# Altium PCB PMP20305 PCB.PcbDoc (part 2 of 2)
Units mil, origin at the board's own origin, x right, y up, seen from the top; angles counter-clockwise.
Board outline 4400 x 7000 mil, 4 copper layers (Top Layer, GND, Signal Layer 2, Bottom Layer), stack 61.2 mil thick; 121 components, 72 nets, 974 pads, 10 vias.
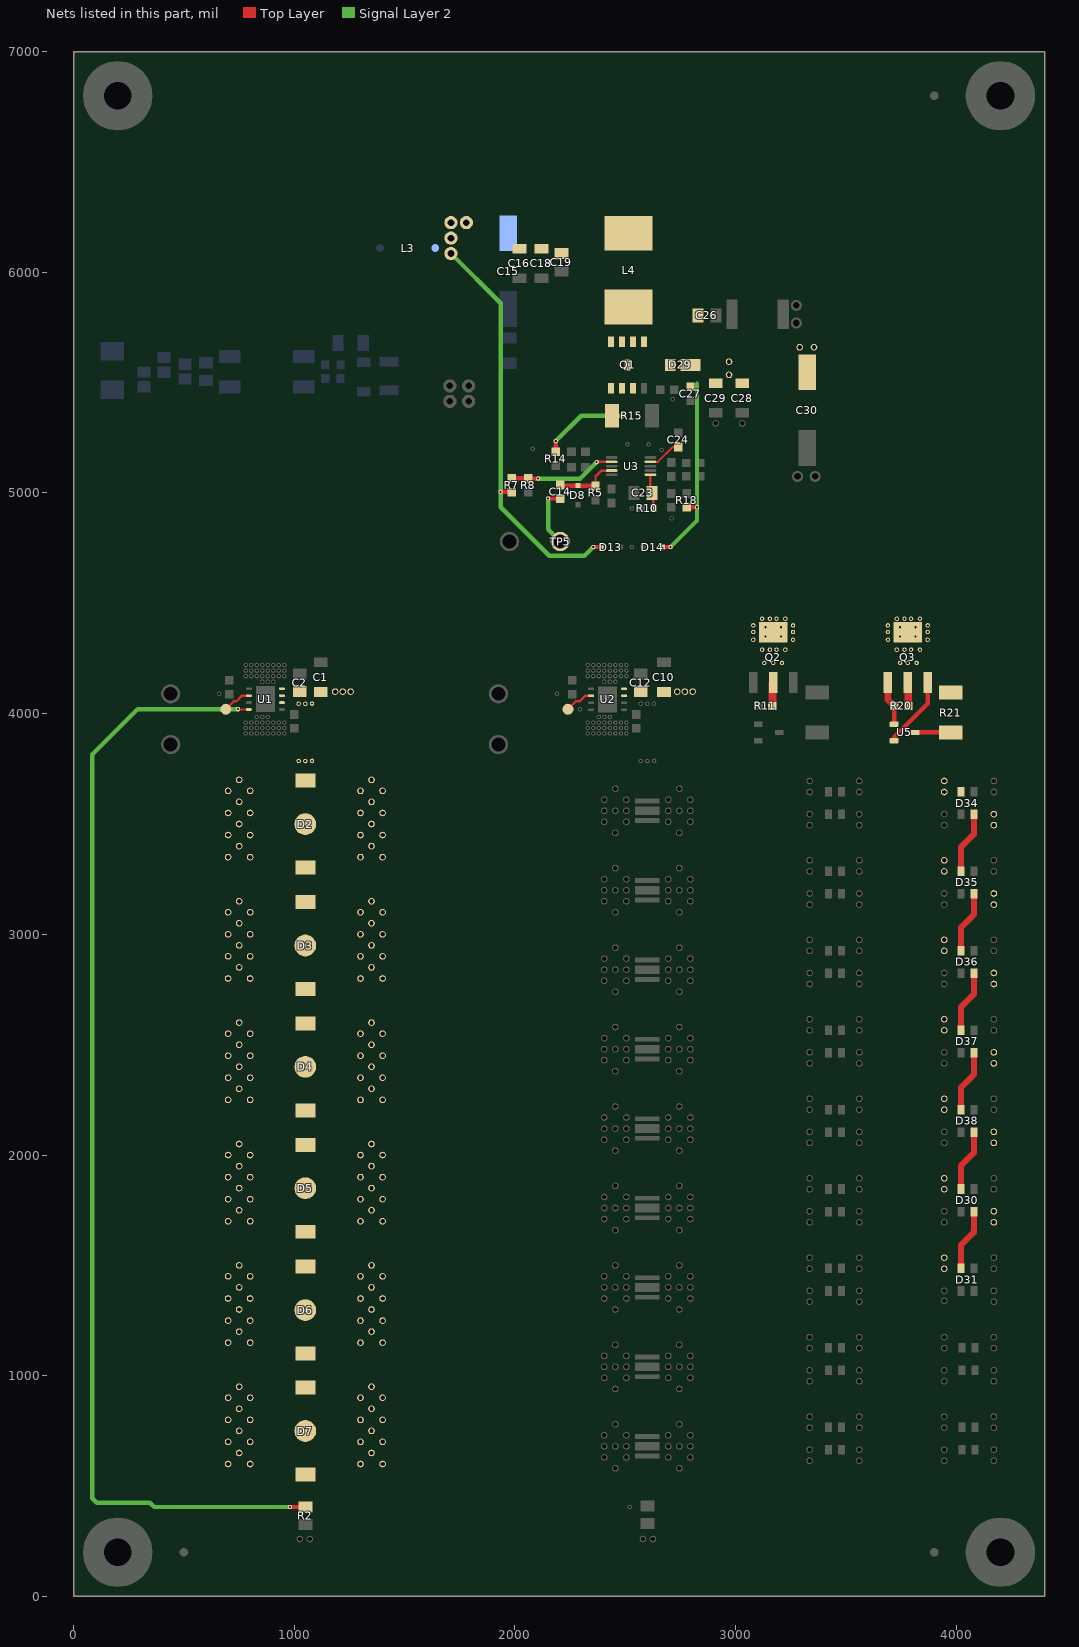
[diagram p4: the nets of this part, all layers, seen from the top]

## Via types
v1: diameter 20, hole 10, Top Layer to Bottom Layer, 10 vias

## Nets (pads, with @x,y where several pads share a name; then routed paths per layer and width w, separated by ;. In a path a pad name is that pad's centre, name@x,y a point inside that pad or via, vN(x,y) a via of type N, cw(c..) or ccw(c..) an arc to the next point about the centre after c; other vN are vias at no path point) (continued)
RED3_3: D30.2 D31.4 pad.124 pad.125 pad.128 pad.129 | length 282.1
  Top Layer w28: D31.4@4020.47,1486.18 4020.47,1590.47 4079.53,1649.53 D30.2@4079.53,1743.82
RED3_4: D30.4 D38.2 pad.132 pad.133 pad.136 pad.137 | length 282.1
  Top Layer w28: D30.4@4020.47,1846.18 4020.47,1950.47 4079.53,2009.53 D38.2@4079.53,2103.82
RED3_5: D37.2 D38.4 pad.140 pad.141 pad.144 pad.145 | length 282.1
  Top Layer w28: D38.4@4020.47,2206.18 4020.47,2305.47 4079.53,2364.53 D37.2@4079.53,2463.82
RED3_6: D36.2 D37.4 pad.148 pad.149 pad.152 pad.153 | length 282.1
  Top Layer w28: D37.4@4020.47,2566.18 4020.47,2670.47 4079.53,2729.53 D36.2@4079.53,2823.82
RED3_7: D35.2 D36.4 pad.158 pad.159 pad.162 pad.163 | length 282.1
  Top Layer w28: D36.4@4020.47,2926.18 4020.47,3030.47 4079.53,3089.53 D35.2@4079.53,3183.82
RED3_8: D34.2 D35.4 pad.166 pad.167 pad.170 pad.171 | length 282.1
  Top Layer w28: D35.4@4020.47,3286.18 4020.47,3394.54 4079.53,3453.59 D34.2@4079.53,3543.82
RED3_9: D34.4 pad.174 pad.175 R21.1 U5.3 | length 162.2
  Top Layer w20: U5.3@3812.24,3915 R21.1@3974.45,3915
RED3_BASE: Q3.1 R20.1 U5.1 | length 201
  Top Layer w10: Q3.1@3688.5,4139.88 Q3.1@3689.45,4140.83
  Top Layer w20: U5.1@3717.76,3952.4 R20.1@3717.76,4034.25
  Top Layer w30: Q3.1@3689.45,4140.83 3689.45,4064.06 R20.1@3718.5,4035
RED3_SNS: Q3.3 R21.2 U5.2 | length 326.5
  Top Layer w20: U5.2@3717.76,3877.6 3717.76,3892.76 3870.55,4045.55 Q3.3@3870.55,4140.83
RSNS: pad.6@2185,5235 pad.6@2490,5350 Q1.1 Q1.2 Q1.3 R14.2 R15.2 | length 404
  Top Layer w10: R14.2@2175.98,5182.78 R14.2@2177.98,5184.77
  Top Layer w20: R14.2@2185,5186.5 pad.6@2185,5235
  Signal Layer 2 w20: pad.6@2185,5235 2300,5350 pad.6@2490,5350
ST_RED: pad.0@2240,4020 U2.2 | length 130.4
  Top Layer w11: pad.0@2240,4020 2275.44,4055.44 2292.07,4055.44 2317.38,4080.75 U2.2@2345.2,4080.75
ST_YEL: pad.0@690,4020 U1.2 | length 129.7
  Top Layer w11: pad.0@690,4020 725.44,4055.44 737.07,4055.44 763.44,4081.81 U1.2@794.14,4081.81
SW: C26.2 D29.2 L4.2 Q1.5 Q1.6 Q1.7 Q1.8 Q1.9
SYNC: C14.2 D8.1 R5.2 U3.9 | length 284.5
  Top Layer w10: U3.9@2437.8,5100.69 U3.9@2438.7,5101.59
  Top Layer w11: R5.2@2365,5031.5 2365,5075 2391.59,5101.59 U3.9@2438.7,5101.59
  Top Layer w20: C14.2@2208.19,5033.31 D8.1@2285,5033.31 R5.2@2363.19,5033.31
SYNCIN: C14.1 pad.6@2150,4975 TP5.1 | length 271.3
  Top Layer w20: pad.6@2150,4975 C14.1@2203.5,4975
  Signal Layer 2 w20: pad.6@2150,4975 2150,4835 TP5.1@2205,4780
UVLO: pad.6@2105,5065 pad.6@2370,5140 R7.1 R8.2 U3.7 | length 482.3
  Top Layer w11: pad.6@2370.96,5140.96 U3.7@2438.7,5140.96
  Top Layer w20: R7.1@1985,5066.5 R8.2@2060,5066.5 ; R8.2@2061.5,5065 pad.6@2105,5065
  Signal Layer 2 w20: pad.6@2105,5065 2295,5065 pad.6@2370,5140
V_BOOST: C1.1 C2.1 C10.1 C12.1 C27.1 C28.1 C29.1 C30.1 D14.2 D29.1 pad.6@2705,4755 pad.6@2825,4935 pad.180 pad.181 pad.182 pad.183 pad.188 pad.189 pad.190 pad.191 pad.192 pad.193 pad.194 pad.195 pad.214 pad.215 pad.216 pad.217 pad.218 pad.219 pad.224 pad.225 Q2.2 Q2.4 Q3.2 Q3.4 R11.2 R18.2 R20.2 U1.7 U1.8 U2.7 U2.8 | length 1079.9
  Top Layer w20: D14.2@2668.31,4755 pad.6@2705,4755 ; R18.2@2778.19,4935 pad.6@2825,4935
  Top Layer w35: R11.2@3166.5,4035 Q2.2@3166.5,4137.32 ; R20.2@3781.5,4035 Q3.2@3781.5,4139.33
  Signal Layer 2 w20: pad.6@2705,4755 2825,4875 pad.6@2825,4935 2825,5495
VCC: C24.2 U3.4 | length 155.4
  Top Layer w10: U3.4@2614.8,5141.87 U3.4@2613.9,5140.96 2647.38,5140.96 2714.92,5208.5 C24.2@2740,5208.5
VIN: C15.1 C16.1 C18.1 C19.1 D13.2 L3.2 L4.1 pad.6@1935,5005 pad.6@2355,4755 pad.198@1710,6225 pad.199@1710,6085 pad.200@1780,6225 pad.201@1710,6155 R7.2 | length 1856.1
  Top Layer w20: pad.6@1935,5005 R7.2@1983.5,5005 ; pad.6@2355,4755 D13.2@2391.69,4755
  Signal Layer 2 w20: pad.199@1710,6085 1935,5860 pad.6@1935,5005 1935,4935 2155,4715 2315,4715 pad.6@2355,4755
VIN_IC: C23.1 R10.1 U3.1 | length 146.9
  Top Layer w11: U3.1@2613.9,5081.91 2613.9,5006.1 C23.1@2620,5000 ; R10.1@2627.56,4930 C23.1@2627.56,4992.44
YEL_1: D6.2 D7.1 pad.176@700,900 pad.176@750,950 pad.176@800,900 pad.176@1300,900 pad.176@1350,950 pad.176@1400,900 pad.177@700,800 pad.177@750,850 pad.177@800,800 pad.177@1300,800 pad.177@1350,850 pad.177@1400,800 pad.178@700,700 pad.178@750,750 pad.178@800,700 pad.178@1300,700 pad.178@1350,750 pad.178@1400,700 pad.179@700,600 pad.179@750,650 pad.179@800,600 pad.179@1300,600 pad.179@1350,650 pad.179@1400,600
YEL_2: D5.2 D6.1 pad.176@700,1450 pad.176@750,1500 pad.176@800,1450 pad.176@1300,1450 pad.176@1350,1500 pad.176@1400,1450 pad.177@700,1350 pad.177@750,1400 pad.177@800,1350 pad.177@1300,1350 pad.177@1350,1400 pad.177@1400,1350 pad.178@700,1250 pad.178@750,1300 pad.178@800,1250 pad.178@1300,1250 pad.178@1350,1300 pad.178@1400,1250 pad.179@700,1150 pad.179@750,1200 pad.179@800,1150 pad.179@1300,1150 pad.179@1350,1200 pad.179@1400,1150
YEL_3: D4.2 D5.1 pad.176@700,2000 pad.176@750,2050 pad.176@800,2000 pad.176@1300,2000 pad.176@1350,2050 pad.176@1400,2000 pad.177@700,1900 pad.177@750,1950 pad.177@800,1900 pad.177@1300,1900 pad.177@1350,1950 pad.177@1400,1900 pad.178@700,1800 pad.178@750,1850 pad.178@800,1800 pad.178@1300,1800 pad.178@1350,1850 pad.178@1400,1800 pad.179@700,1700 pad.179@750,1750 pad.179@800,1700 pad.179@1300,1700 pad.179@1350,1750 pad.179@1400,1700
YEL_4: D3.2 D4.1 pad.176@700,2550 pad.176@750,2600 pad.176@800,2550 pad.176@1300,2550 pad.176@1350,2600 pad.176@1400,2550 pad.177@700,2450 pad.177@750,2500 pad.177@800,2450 pad.177@1300,2450 pad.177@1350,2500 pad.177@1400,2450 pad.178@700,2350 pad.178@750,2400 pad.178@800,2350 pad.178@1300,2350 pad.178@1350,2400 pad.178@1400,2350 pad.179@700,2250 pad.179@750,2300 pad.179@800,2250 pad.179@1300,2250 pad.179@1350,2300 pad.179@1400,2250
YEL_5: D2.2 D3.1 pad.176@700,3100 pad.176@750,3150 pad.176@800,3100 pad.176@1300,3100 pad.176@1350,3150 pad.176@1400,3100 pad.177@700,3000 pad.177@750,3050 pad.177@800,3000 pad.177@1300,3000 pad.177@1350,3050 pad.177@1400,3000 pad.178@700,2900 pad.178@750,2950 pad.178@800,2900 pad.178@1300,2900 pad.178@1350,2950 pad.178@1400,2900 pad.179@700,2800 pad.179@750,2850 pad.179@800,2800 pad.179@1300,2800 pad.179@1350,2850 pad.179@1400,2800
YEL_6: D2.1 pad.1@1020,3785.49 pad.1@1020,4045 pad.1@1050,3785 pad.1@1050,4044.51 pad.1@1080.49,3785.98 pad.1@1080.49,4045.49 pad.176@700,3650 pad.176@750,3700 pad.176@800,3650 pad.176@1300,3650 pad.176@1350,3700 pad.176@1400,3650 pad.177@700,3550 pad.177@750,3600 pad.177@800,3550 pad.177@1300,3550 pad.177@1350,3600 pad.177@1400,3550 pad.178@700,3450 pad.178@750,3500 pad.178@800,3450 pad.178@1300,3450 pad.178@1350,3500 pad.178@1400,3450 pad.179@700,3350 pad.179@750,3400 pad.179@800,3350 pad.179@1300,3350 pad.179@1350,3400 pad.179@1400,3350 U1.6
YEL_SNS: D7.2 pad.1@745,4020.49 pad.1@980,405 R2.2 U1.4 | length 5143.5
  Top Layer w11: pad.1@746.67,4018.82 U1.4@794.14,4018.82
  Top Layer w20: pad.1@980,405 R2.2@1050,405
  Signal Layer 2 w20: pad.1@744.51,4020 290,4020 85,3815 85,445 105,425 345,425 365,405 pad.1@980,405
pads on no net: D20.1 D20.3 D21.1 D21.3 D22.1 D22.3 D23.1 D23.3 D24.1 D24.3 D25.1 D25.3 D26.1 D26.3 D27.1 D27.3 D28.1 D28.3 D30.1 D30.3 D31.1 D31.3 D32.1 D32.3 D33.1 D33.3 D34.1 D34.3 D35.1 D35.3 D36.1 D36.3 D37.1 D37.3 D38.1 D38.3 FID1.1 FID2.1 FID3.1 H1.1 H2.1 H3.1 H4.1 H5.0 H6.0 H7.0 H8.0 LBL1.0

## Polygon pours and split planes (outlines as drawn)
RED1_9 on Top Layer "TopLayer-RED1_9" (solid, remove dead copper, pour order 294): 2485,4045 2485,4060 2655,4060 2655,4035 2485,4035 2485,4045
YEL_6 on Top Layer "TopLayer-YEL_6" (solid, remove dead copper, pour order 136): 930,4050 930,4060 1015,4060 1095,4060 1095,4035 930,4035 930,4050
GND on Top Layer "Top Layer-GND" (solid, remove dead copper, pour order 296): 1650,7000 4400,7000 4400,4720 4400,0 0,0 0,5050 1650,5050 1650,5350
V_BOOST on Top Layer "Top Layer-Vboost" (solid, remove dead copper, pour order 106): 2750,5700 2750,5460 3400,5460 3400,4500 2990,4500 2990,3990 3400,3990 4400,3990 4400,5460 4400,5700
SW on Top Layer "Top Layer-SW" (solid, remove dead copper, pour order 105): 2395,5920 2730,5920 2730,5835 2855,5835 2855,5775 2730,5775 2730,5530 2395,5530
FB on Top Layer "Top Layer-FB" (solid, remove dead copper, pour order 102): 2800,5095 2800,4976.28 2689.28,4976.28 2689.28,5084.63 2689.28,5090 2689.28,5095
VIN on Top Layer "Top Layer-VIN" (solid, remove dead copper, pour order 101): 1652.5,6255 2627.5,6255 2627.5,6050 2017.5,6050 1652.5,6050
RSNS on Top Layer "Bottom Layer-Rsns" (solid, remove dead copper, pour order 104): 2390,5500 2390,5295 2550,5295 2550,5500
HS on Top Layer "Top Layer-HS" (solid, remove dead copper, pour order 131): 3100,3750 3100,500 2100,500 2100,3750
YEL_6 on Top Layer "Top Layer-YEL_6" (solid, remove dead copper, pour order 125): 150,3775 1950,3775 1950,3235 150,3235
YEL_5 on Top Layer "Top Layer-YEL_5" (solid, remove dead copper, pour order 126): 150,3215 150,2685 1950,2685 1950,3215
YEL_4 on Top Layer "Top Layer-YEL_4" (solid, remove dead copper, pour order 127): 150,2650 150,2665 1950,2665 1950,2650 1950,2135 150,2135
YEL_3 on Top Layer "Top Layer-YEL_3" (solid, remove dead copper, pour order 128): 150,2115 1950,2115 1950,1585 150,1585
YEL_2 on Top Layer "Top Layer-YEL_2" (solid, remove dead copper, pour order 129): 150,1565 150,1035 1950,1035 1950,1565
YEL_1 on Top Layer "Top Layer-YEL_1" (solid, remove dead copper, pour order 130): 150,1015 1950,1015 1950,475 150,475
V_BOOST on Top Layer "TopLayer-V_BOOST_YEL" (solid, remove dead copper, pour order 132): 930,4115 930,4125 1275,4125 1275,4105 1275,4075 970,4075 930,4075
V_BOOST on Top Layer "TopLayer-V_BOOST_RED1" (solid, remove dead copper, pour order 134): 2485,4125 2830,4125 2830,4075 2485,4075
GND on Bottom Layer "BottomLayer-GND" (solid, remove dead copper, pour order 324): 0,5050 1650,5050 1650,5225.25 1650,5377.5 1272.5,5377.5 1000,5377.5 1000,5505 1125,5505 1125,5535 1215.65,5535 1270.65,5480 1460,5480 1650,5480 1650,5615 1650,7000 4400,7000 4400,0 0,0
BEAD_OUT on Bottom Layer "BottomLayer-BEAD_OUT" (solid, remove dead copper, pour order 320): 1475,5570 1285,5570 1285,5715 1370,5715 1370,6260 1475,6260 1475,5865
CM_OUT on Bottom Layer "BottomLayer-CM_OUT" (solid, remove dead copper, pour order 318): 1230,5565 1120,5565 1120,5590 995,5590 995,5650 1170,5650 1170,5715 1230,5715 1230,5565
GNDIN on Bottom Layer "BottomLayer-GNDin" (solid, remove dead copper, pour order 316): 755,5495 755,5510 635,5510 635,5535 535,5535 535,5540 475,5540 475,5505 240,5505 85,5505 85,5150 400,5150 400,5240 400,5450 695,5450 755,5450
CM_IN on Bottom Layer "BottomLayer-CM_IN" (solid, remove dead copper, pour order 314): 755,5590 635,5590 635,5565 535,5565 535,5560 475,5560 475,5590 380,5590 380,5600 370,5600 85,5600 85,6000 400,6000 400,5650 755,5650 755,5590
VIN on Bottom Layer "BottomLayer-VIN" (solid, remove dead copper, pour order 322): 1655,5960 1555.42,5960 1555.42,5984.48 1555.42,6260 2015.42,6260 2015.42,5984.48 2015.42,5960
RED1_9 on Signal Layer 2 "SignalLayer2-RED1_9" (solid, remove dead copper, pour order 308): 2545,4060 2655,4060 2655,3890 2655,3625 2655,3585 2545,3585 2545,3605 2545,3725 2545,4000
YEL_6 on Signal Layer 2 "SignalLayer2-YEL_6" (solid, remove dead copper, pour order 306): 1005,4060 1095,4060 1095,3805 1095,3765 1005,3765 1005,3995
GND on Signal Layer 2 "SignalLayer2-GND" (solid, remove dead copper, pour order 312): 1650,5050 1650,5350 1650,7000 4400,7000 4400,0 0,0 0,5050
V_BOOST on Signal Layer 2 "SignalLayer2-V_BOOST" (solid, remove dead copper, pour order 304): 2750,5460 2750,5540 2750,5700 4400,5700 4400,5645 4400,3990 3680,3990 2990,3990 2990,4235 2825,4235 2825,4075 2715,4075 2715,4380 1275,4380 1275,4075 1165,4075 1165,4500 2990,4500 3400,4500 3400,5460 3385,5460
GND on GND "SignalLayer1-GND" (solid, remove dead copper, pour order 300): 0,5050 1650,5050 1650,7000 4400,7000 4400,0 0,0

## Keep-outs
Keep-Out Layer:
  the board outline again, w10
  text ".Layer_Name" at 577,-858.49 h60

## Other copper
Top Layer:
  rectangle net RED2_9: 3315,3680 3435,3945
  rectangle net RED2_SNS: 3240,4060 3425,4190
  rectangle net RED3_9: 3920,3680 4035,3945
  rectangle net RED3_SNS: 3850,4065 4030,4190
  rectangle net RED1_9: 2545,3595 2655,3800
  rectangle net YEL_6: 1005,3665 1095,3800
  rectangle net RED2_1: 3465,920 3725,1045
  rectangle net RED2_2: 3465,1280 3725,1405
  rectangle net RED2_3: 3465,1640 3725,1765
  rectangle net RED2_4: 3465,2000 3725,2125
  rectangle net RED2_5: 3465,2360 3725,2485
  rectangle net RED2_6: 3465,2720 3725,2845
  rectangle net RED2_7: 3465,3080 3725,3205
  rectangle net RED2_8: 3465,3440 3725,3565
  rectangle net RED3_8: 4065,3440 4325,3565
  rectangle net RED3_7: 4065,3080 4325,3205
  rectangle net RED3_6: 4065,2720 4325,2845
  rectangle net RED3_5: 4065,2360 4325,2485
  rectangle net RED3_4: 4065,2000 4325,2125
  rectangle net RED3_3: 4065,1640 4325,1765
  rectangle net RED3_2: 4065,1280 4325,1405
  rectangle net RED3_1: 4070,920 4325,1045
  rectangle net RED3_1: 3775,745 4040,870
  rectangle net RED3_2: 3775,1105 4040,1230
  rectangle net RED3_3: 3775,1465 4035,1590
  rectangle net RED3_4: 3775,1825 4035,1950
  rectangle net RED3_5: 3775,2185 4035,2310
  rectangle net RED3_6: 3775,2545 4035,2670
  rectangle net RED3_7: 3775,2905 4035,3030
  rectangle net RED3_8: 3775,3265 4035,3390
  rectangle net RED3_9: 3775,3625 4035,3750
  rectangle net RED2_9: 3175,3625 3435,3750
  rectangle net RED2_8: 3175,3265 3435,3390
  rectangle net RED2_7: 3175,2905 3435,3030
  rectangle net RED2_6: 3175,2545 3435,2670
  rectangle net RED2_5: 3175,2185 3435,2310
  rectangle net RED2_4: 3175,1825 3435,1950
  rectangle net RED2_3: 3175,1465 3435,1590
  rectangle net RED2_2: 3175,1105 3435,1230
  rectangle net RED2_1: 3175,745 3435,870
  rectangle: 3775,3440 4035,3565
  rectangle: 3775,3080 4035,3205
  rectangle: 3775,2720 4035,2845
  rectangle: 3775,2360 4035,2485
  rectangle: 3775,2000 4035,2125
  rectangle: 3775,1640 4035,1765
  rectangle: 3775,1280 4035,1405
  rectangle: 3775,920 4040,1045
  rectangle: 3775,560 4040,685
  rectangle: 3175,560 3435,685
  rectangle: 3175,920 3435,1045
  rectangle: 3175,1280 3435,1405
  rectangle: 3175,1640 3435,1765
  rectangle: 3175,2000 3435,2125
  rectangle: 3175,2360 3435,2485
  rectangle: 3175,2720 3435,2845
  rectangle: 3175,3080 3435,3205
  rectangle: 3175,3440 3435,3565
  rectangle: 4065,3625 4325,3750
  rectangle: 4065,3265 4325,3390
  rectangle: 4065,2905 4325,3030
  rectangle: 4065,2545 4325,2670
  rectangle: 4065,2185 4325,2310
  rectangle: 4065,1825 4325,1950
  rectangle: 4065,1465 4325,1590
  rectangle: 4070,1105 4325,1230
  rectangle: 4070,745 4325,870
  rectangle: 3465,3625 3725,3750
  rectangle: 3465,3265 3725,3390
  rectangle: 3465,2905 3725,3030
  rectangle: 3465,2545 3725,2670
  rectangle: 3465,2185 3725,2310
  rectangle: 3465,1825 3725,1950
  rectangle: 3465,1465 3725,1590
  rectangle: 3465,1105 3725,1230
  rectangle: 3465,745 3725,870
  rectangle net YEL_SNS: 1005,380 1095,580
  rectangle net RED1_SNS: 2545,385 2655,645
  rectangle net YEL_1: 1005,915 1095,1130
  rectangle net YEL_2: 1005,1465 1095,1680
  rectangle net YEL_3: 1005,2015 1095,2230
  rectangle net YEL_4: 1005,2565 1095,2780
  rectangle net YEL_5: 1005,3115 1095,3330
  rectangle net RED1_1: 2545,715 2655,1005
  rectangle net RED1_2: 2545,1075 2655,1365
  rectangle net RED1_3: 2545,1435 2655,1725
  rectangle net RED1_4: 2545,1795 2655,2085
  rectangle net RED1_5: 2545,2155 2655,2445
  rectangle net RED1_6: 2545,2515 2655,2805
  rectangle net RED1_7: 2545,2875 2655,3165
  rectangle net RED1_8: 2545,3235 2655,3525
  text ".Layer_Name" at 577,-858.49 h60
GND:
  rectangle net RED3_8: 4065,3440 4325,3565
  rectangle net RED3_7: 4065,3080 4325,3205
  rectangle net RED3_6: 4065,2720 4325,2845
  rectangle net RED3_5: 4065,2360 4325,2485
  rectangle net RED3_4: 4065,2000 4325,2125
  rectangle net RED3_3: 4065,1640 4325,1765
  rectangle net RED3_2: 4065,1280 4325,1405
  rectangle net RED2_2: 3465,1280 3725,1405
  rectangle net RED2_3: 3465,1640 3725,1765
  rectangle net RED2_4: 3465,2000 3725,2125
  rectangle net RED2_5: 3465,2360 3725,2485
  rectangle net RED2_6: 3465,2720 3725,2845
  rectangle net RED2_7: 3465,3080 3725,3205
  rectangle net RED2_8: 3465,3440 3725,3565
  rectangle: 3775,560 4040,685
  rectangle net RED3_1: 3775,745 4040,870
  rectangle: 4070,745 4325,870
  rectangle net RED3_1: 4070,920 4325,1045
  rectangle: 3775,920 4040,1045
  rectangle net RED3_2: 3775,1105 4040,1230
  rectangle: 4070,1105 4325,1230
  rectangle: 3775,1280 4035,1405
  rectangle net RED3_3: 3775,1465 4035,1590
  rectangle: 4065,1465 4325,1590
  rectangle: 3775,1640 4035,1765
  rectangle net RED3_4: 3775,1825 4035,1950
  rectangle: 4065,1825 4325,1950
  rectangle: 3775,2000 4035,2125
  rectangle net RED3_5: 3775,2185 4035,2310
  rectangle: 4065,2185 4325,2310
  rectangle: 3775,2360 4035,2485
  rectangle net RED3_6: 3775,2545 4035,2670
  rectangle: 4065,2545 4325,2670
  rectangle: 3775,2720 4035,2845
  rectangle: 4065,2905 4325,3030
  rectangle net RED3_7: 3775,2905 4035,3030
  rectangle: 3775,3080 4035,3205
  rectangle: 4065,3265 4325,3390
  rectangle net RED3_8: 3775,3265 4035,3390
  rectangle: 3775,3440 4035,3565
  rectangle: 4065,3625 4325,3750
  rectangle net RED3_9: 3775,3625 4035,3750
  rectangle: 3465,3625 3725,3750
  rectangle net RED2_9: 3175,3625 3435,3750
  rectangle: 3175,3440 3435,3565
  rectangle: 3465,3265 3725,3390
  rectangle net RED2_8: 3175,3265 3435,3390
  rectangle: 3175,3080 3435,3205
  rectangle: 3465,2905 3725,3030
  rectangle net RED2_7: 3175,2905 3435,3030
  rectangle: 3175,2720 3435,2845
  rectangle: 3465,2545 3725,2670
  rectangle net RED2_6: 3175,2545 3435,2670
  rectangle: 3175,2360 3435,2485
  rectangle: 3465,2185 3725,2310
  rectangle net RED2_5: 3175,2185 3435,2310
  rectangle: 3175,2000 3435,2125
  rectangle: 3465,1825 3725,1950
  rectangle net RED2_4: 3175,1825 3435,1950
  rectangle: 3175,1640 3435,1765
  rectangle net RED2_3: 3175,1465 3435,1590
  rectangle: 3465,1465 3725,1590
  rectangle: 3175,1280 3435,1405
  rectangle: 3465,1105 3725,1230
  rectangle net RED2_2: 3175,1105 3435,1230
  rectangle: 3175,920 3435,1045
  rectangle net RED2_1: 3465,920 3725,1045
  rectangle: 3465,745 3725,870
  rectangle net RED2_1: 3175,745 3435,870
  rectangle: 3175,560 3435,685
  rectangle net YEL_6: 150,3250 1950,3750
  rectangle net YEL_5: 150,2700 1950,3200
  rectangle net YEL_4: 150,2150 1950,2650
  rectangle net YEL_3: 150,1600 1950,2100
  rectangle net YEL_2: 150,1050 1950,1550
  rectangle net YEL_1: 150,500 1950,1000
  rectangle net HS: 2100,500 3100,3750
Signal Layer 2:
  rectangle net RED3_1: 4070,920 4325,1045
  rectangle net RED3_2: 4065,1280 4325,1405
  rectangle net RED3_3: 4065,1640 4325,1765
  rectangle net RED3_4: 4065,2000 4325,2125
  rectangle net RED3_5: 4065,2360 4325,2485
  rectangle net RED3_6: 4065,2720 4325,2845
  rectangle net RED3_7: 4065,3080 4325,3205
  rectangle net RED3_8: 4065,3440 4325,3565
  rectangle net RED2_8: 3465,3440 3725,3565
  rectangle net RED2_7: 3465,3080 3725,3205
  rectangle net RED2_6: 3465,2720 3725,2845
  rectangle net RED2_5: 3465,2360 3725,2485
  rectangle net RED2_4: 3465,2000 3725,2125
  rectangle net RED2_3: 3465,1640 3725,1765
  rectangle net RED2_2: 3465,1280 3725,1405
  rectangle net RED2_1: 3465,920 3725,1045
  rectangle net RED3_2: 3775,1105 4040,1230
  rectangle: 3775,1280 4035,1405
  rectangle net RED3_3: 3775,1465 4035,1590
  rectangle: 3775,1640 4035,1765
  rectangle net RED3_4: 3775,1825 4035,1950
  rectangle: 3775,2000 4035,2125
  rectangle net RED3_5: 3775,2185 4035,2310
  rectangle: 3775,2360 4035,2485
  rectangle net RED3_6: 3775,2545 4035,2670
  rectangle: 3775,2720 4035,2845
  rectangle net RED3_7: 3775,2905 4035,3030
  rectangle: 3775,3080 4035,3205
  rectangle net RED3_8: 3775,3265 4035,3390
  rectangle: 3775,3440 4035,3565
  rectangle net RED3_9: 3775,3625 4035,3750
  rectangle: 4065,3625 4325,3750
  rectangle: 4065,3265 4325,3390
  rectangle: 4065,2905 4325,3030
  rectangle: 4065,2545 4325,2670
  rectangle: 4065,2185 4325,2310
  rectangle: 4065,1825 4325,1950
  rectangle: 4065,1465 4325,1590
  rectangle: 4070,1105 4325,1230
  rectangle: 3775,920 4040,1045
  rectangle: 4070,745 4325,870
  rectangle net RED3_1: 3775,745 4040,870
  rectangle: 3775,560 4040,685
  rectangle: 3175,560 3435,685
  rectangle: 3465,745 3725,870
  rectangle net RED2_1: 3175,745 3435,870
  rectangle: 3175,920 3435,1045
  rectangle: 3465,1105 3725,1230
  rectangle net RED2_2: 3175,1105 3435,1230
  rectangle: 3175,1280 3435,1405
  rectangle: 3465,1465 3725,1590
  rectangle net RED2_3: 3175,1465 3435,1590
  rectangle: 3175,1640 3435,1765
  rectangle: 3465,1825 3725,1950
  rectangle net RED2_4: 3175,1825 3435,1950
  rectangle: 3175,2000 3435,2125
  rectangle: 3465,2185 3725,2310
  rectangle net RED2_5: 3175,2185 3435,2310
  rectangle: 3175,2360 3435,2485
  rectangle: 3465,2545 3725,2670
  rectangle net RED2_6: 3175,2545 3435,2670
  rectangle: 3175,2720 3435,2845
  rectangle: 3465,2905 3725,3030
  rectangle net RED2_7: 3175,2905 3435,3030
  rectangle: 3175,3080 3435,3205
  rectangle: 3465,3265 3725,3390
  rectangle net RED2_8: 3175,3265 3435,3390
  rectangle: 3175,3440 3435,3565
  rectangle: 3465,3625 3725,3750
  rectangle net RED2_9: 3175,3625 3435,3750
  rectangle net HS: 2100,500 3100,3750
  rectangle net YEL_1: 150,500 1950,1000
  rectangle net YEL_2: 150,1050 1950,1550
  rectangle net YEL_3: 150,1600 1950,2100
  rectangle net YEL_4: 150,2150 1950,2650
  rectangle net YEL_5: 150,2700 1950,3200
  rectangle net YEL_6: 150,3250 1950,3750
Bottom Layer:
  rectangle net RED3_1: 4070,920 4325,1045
  rectangle net RED3_2: 4065,1280 4325,1405
  rectangle net RED3_3: 4065,1640 4325,1765
  rectangle net RED3_4: 4065,2000 4325,2125
  rectangle net RED3_5: 4065,2360 4325,2485
  rectangle net RED3_6: 4065,2720 4325,2845
  rectangle net RED3_7: 4065,3080 4325,3205
  rectangle net RED3_8: 4065,3440 4325,3565
  rectangle net RED2_8: 3465,3440 3725,3565
  rectangle net RED2_7: 3465,3080 3725,3205
  rectangle net RED2_6: 3465,2720 3725,2845
  rectangle net RED2_5: 3465,2360 3725,2485
  rectangle net RED2_4: 3465,2000 3725,2125
  rectangle net RED2_3: 3465,1640 3725,1765
  rectangle net RED2_2: 3465,1280 3725,1405
  rectangle net RED2_1: 3465,920 3725,1045
  rectangle: 4070,745 4325,870
  rectangle: 4070,1105 4325,1230
  rectangle: 4065,1465 4325,1590
  rectangle: 4065,1825 4325,1950
  rectangle: 4065,2185 4325,2310
  rectangle: 4065,2545 4325,2670
  rectangle: 4065,2905 4325,3030
  rectangle: 4065,3265 4325,3390
  rectangle: 4065,3625 4325,3750
  rectangle net RED3_9: 3775,3625 4035,3750
  rectangle: 3775,3440 4035,3565
  rectangle net RED3_8: 3775,3265 4035,3390
  rectangle: 3775,3080 4035,3205
  rectangle net RED3_7: 3775,2905 4035,3030
  rectangle: 3775,2720 4035,2845
  rectangle net RED3_6: 3775,2545 4035,2670
  rectangle: 3775,2360 4035,2485
  rectangle net RED3_5: 3775,2185 4035,2310
  rectangle: 3775,2000 4035,2125
  rectangle net RED3_4: 3775,1825 4035,1950
  rectangle: 3775,1640 4035,1765
  rectangle net RED3_3: 3775,1465 4035,1590
  rectangle: 3775,1280 4035,1405
  rectangle net RED3_2: 3775,1105 4040,1230
  rectangle: 3775,920 4040,1045
  rectangle net RED3_1: 3775,745 4040,870
  rectangle: 3775,560 4040,685
  rectangle: 3465,745 3725,870
  rectangle: 3465,1105 3725,1230
  rectangle: 3465,1465 3725,1590
  rectangle: 3465,1825 3725,1950
  rectangle: 3465,2185 3725,2310
  rectangle: 3465,2545 3725,2670
  rectangle: 3465,2905 3725,3030
  rectangle: 3465,3265 3725,3390
  rectangle: 3465,3625 3725,3750
  rectangle net RED2_9: 3175,3625 3435,3750
  rectangle: 3175,3440 3435,3565
  rectangle net RED2_8: 3175,3265 3435,3390
  rectangle: 3175,3080 3435,3205
  rectangle net RED2_7: 3175,2905 3435,3030
  rectangle: 3175,2720 3435,2845
  rectangle net RED2_6: 3175,2545 3435,2670
  rectangle: 3175,2360 3435,2485
  rectangle net RED2_5: 3175,2185 3435,2310
  rectangle: 3175,2000 3435,2125
  rectangle net RED2_4: 3175,1825 3435,1950
  rectangle: 3175,1640 3435,1765
  rectangle net RED2_3: 3175,1465 3435,1590
  rectangle: 3175,1280 3435,1405
  rectangle net RED2_2: 3175,1105 3435,1230
  rectangle: 3175,920 3435,1045
  rectangle net RED2_1: 3175,745 3435,870
  rectangle: 3175,560 3435,685
  rectangle net YEL_6: 150,3250 1950,3750
  rectangle net YEL_5: 150,2700 1950,3200
  rectangle net YEL_4: 150,2150 1950,2650
  rectangle net YEL_3: 150,1600 1950,2100
  rectangle net YEL_2: 150,1050 1950,1550
  rectangle net YEL_1: 150,500 1950,1000
  rectangle net HS: 2100,500 3100,3750
  text ".Layer_Name" at 577,-858.49 h60

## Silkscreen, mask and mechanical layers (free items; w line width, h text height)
Top Overlay:
  text "ST_Yellow" at 440,3945 h72.83
  text "ST_Red" at 1990,3940 h72.83
  text ".PRJ_Number" at 1305,110 h60
  text ".PCB_Rev" at 2455,110 h60
  text ".Layer_Name" at 577,-858.49 h60
Bottom Overlay:
  text "Vin" at 450,5850 h100 r270
  text "GNDin" at 450,5120 h100 r270
  text ".Layer_Name" at 577,-858.49 h60
Top Paste:
  text ".Layer_Name" at 577,-858.49 h60
Bottom Paste:
  text ".Layer_Name" at 577,-858.49 h60
Top Solder:
  text ".Layer_Name" at 577,-858.49 h60
  text ".Layer_Name" at 577,-858.49 h60
Bottom Solder:
  rectangle: 85,5150 400,5350
  rectangle: 85,5800 400,6000
  text ".Layer_Name" at 577,-858.49 h60
Drill Guide:
  text ".Layer_Name" at 577,-858.49 h60
M1 Board Outline:
  the board outline again, w10
  text ".Layer_Name" at 577,-858.49 h60
M2 Board Dimensions:
  rectangle: 125,-400 500,-275
  rectangle: 0,-275 125,-150
  lines w7: 0,-275 1000,-275 ; 125,-400 125,-150 ; 250,-400 250,-150 ; 500,-400 500,-150 ; 750,-400 750,-150 ; 0,-400 0,-150 1000,-150 1000,-400 0,-400
  text ".Layer_Name" at 577,-858.49 h60
M3 3D STEP Top:
  text ".Layer_Name" at 577,-858.49 h60
M4 3D STEP Bottom:
  text ".Layer_Name" at 577,-858.49 h60
M5 Assembly Top:
  lines w10: -292,-930.17 6308,-930.17 ; -292,-726.83 6310,-726.83 ; -292,-523.5 -292,-1133.5 3713,-1133.5 6310,-1133.5 6310,-523.5 -291.5,-523.5 -291.5,-1133.5 1284,-1133.5 ; 2173,-1133.5 2173,-523.5 ; 3440,-726.83 3440,-523.5 ; 4280,-726.83 4280,-523.5 ; 4902,-1140 4902,-937.17
  text "COMPONENTS MARKED 'DNP' SHOULD NOT BE POPULATED." at 1153.5,-318.5 h60
  text "ASSEMBLY VARIANT:" at 1153,-434 h60
  text ".VariantName" at 2189,-434 h60
  text "PCB VIEWED FROM TOP SIDE" at -228.5,-655.67 h60
  text "BOARD #:" at 2248,-655.67 h60
  text ".PRJ_Number" at 2793.5,-655.67 h60
  text "REV:" at 3638,-655.67 h60
  text ".PCB_Rev" at 3929.5,-655.67 h60
  text "SVN REV:" at 4476,-655.67 h60
  text ".VersionControl_RevNumber" at 4982,-655.67 h60
  text "TID #:" at 2248,-859 h60
  text ".TID" at 2793.5,-859 h60
  text "PLOT NAME =" at -228.5,-1064.34 h60
  text ".plot_File_Name" at 577,-1064.34 h60
  text "GENERATED    :" at 2250,-1064.34 h60
  text ".Print_Date" at 3119.5,-1064.34 h60
  text ".Print_Time" at 3848.5,-1064.34 h60
  text "TEXAS INSTRUMENTS" at 5113,-1064.34 h60
M6 Assembly Bottom:
  lines w10: -292.5,-727.33 6309.5,-727.33 ; -290.5,-930.67 6309.5,-930.67 ; 1115.5,-1140.5 1115.5,-937.67 ; 1737.5,-727.33 1737.5,-524 ; 2577.5,-727.33 2577.5,-524 ; 3844.5,-1134 3844.5,-524 ; 4733.5,-1134 6309,-1134 6309,-524 -292.5,-524 -292.5,-1134 2304.5,-1134 6309.5,-1134 6309.5,-524
  text "COMPONENTS MARKED 'DNP' SHOULD NOT BE POPULATED." at 6102,-318 h60
  text ".VariantName" at 5058,-434 h60
  text "ASSEMBLY VARIANT:" at 6097,-434 h60
  text ".VersionControl_RevNumber" at 1035.5,-656.17 h60
  text "SVN REV:" at 1541.5,-656.17 h60
  text ".PCB_Rev" at 2088,-656.17 h60
  text "REV:" at 2379.5,-656.17 h60
  text ".PRJ_Number" at 3224,-656.17 h60
  text "BOARD #:" at 3769.5,-656.17 h60
  text "PCB VIEWED FROM BOTTOM SIDE" at 6246,-656.17 h60
  text ".TID" at 3224,-859.5 h60
  text "TID #:" at 3769.5,-859.5 h60
  text "TEXAS INSTRUMENTS" at 904.5,-1064.84 h60
  text ".Print_Time" at 2169,-1064.84 h60
  text ".Print_Date" at 2898,-1064.84 h60
  text "GENERATED    :" at 3767.5,-1064.84 h60
  text ".plot_File_Name" at 5440.5,-1064.84 h60
  text "PLOT NAME =" at 6246,-1064.84 h60
M9 Title Sheet:
  drawing of 57 lines, arcs and shapes, not listed
  text "1" at 739.84,8036.5 h70
  text "2" at 3235.5,8036.5 h70
  text "3" at 5724.84,8036.5 h70
  text "4" at 8231.51,8036.5 h70
  text "5" at 10730.5,8036.5 h70
  text "6" at 13235.5,8036.5 h70
  text "A" at -416.5,6893.5 h70
  text "A" at 14383.5,6893.5 h70
  text "B" at -416.5,4513.5 h70
  text "B" at 14383.5,4513.5 h70
  text "C" at -416.5,2138.5 h70
  text "C" at 14383.5,2138.5 h70
  text "PROJECT TITLE:" at 11343.5,277.5 h45
  text ".PRJ_Title" at 11393.5,144.17 h70
  text "DESIGNED FOR:" at 11343.5,-23.5 h45
  text ".PRJ_Customer" at 11393.5,-163.5 h70
  text "D" at -416.5,-231.5 h70
  text "D" at 14383.5,-231.5 h70
  text "FILE NAME:" at 11343.5,-323.5 h45
  text ".PCB_File_Name_No_Path" at 11393.5,-443.5 h70
  text "Texas Instruments (TI) and/or its licensors do not warrant the accuracy or completeness of this specification" at 6374,-605.34 h45
  text "ENGINEER:" at 11343.5,-613.5 h45
  text "LAYOUT BY:" at 12848.5,-613.5 h45
  text "or any information contained therein. TI and/or its licensors do not warrant that this design will meet" at 6329.01,-718 h45
  text ".PRJ_Engineer" at 11393.5,-768.49 h70
  text ".PCB_Layout" at 12899,-768.49 h70
  text "the specifications, will be suitable for your application or fit for any particular purpose, or will operate in" at 6329.01,-830.67 h45
  text ".Layer_Name" at 577,-858.49 h60
  text "ALTIUM DESIGNER VERSION:" at 12848.5,-923.5 h45
  text "an implementation. TI and/or its licensors do not warrant that the design is production worthy. You should" at 6329.01,-943.33 h45
  text "completely validate and test your design implementation to confirm the system functionality for your application." at 6374,-1056 h45
  text ".print_Scale" at 11393.5,-1056.83 h70
  text ".Application_BuildNumber" at 12899,-1056.83 h70
  text "1" at 739.84,-1263.5 h70
  text "2" at 3235.5,-1263.5 h70
  text "3" at 5724.84,-1263.5 h70
  text "4" at 8231.51,-1263.5 h70
  text "5" at 10730.5,-1263.5 h70
  text "6" at 13235.5,-1263.5 h70
M10 Fab Notes:
  drawing of 173 lines, arcs and shapes, not listed
  text "DESIGN INFORMATION" at 12377.02,6201 h60
  text "MIN. TRACK WIDTH:" at 11732.46,6021 h60
  text "8" at 12828.7,6021 h60
  text "MIL" at 12983.46,6021 h60
  text "MIN. CLEARANCE:" at 11732.46,5889 h60
  text "0.2" at 12768.7,5889 h60
  text "mm" at 12983.46,5889 h60
  text "MIN. VIA PAD SIZE:" at 11732.46,5757 h60
  text "20" at 12798.71,5757 h60
  text "MIL" at 12983.46,5757 h60
  text "0.127mm (5MIL)" at 12427.46,5615.29 h60
  text "MINIMUM ANNULAR RING" at 11403.23,5611 h60
  text "EXTERNAL" at 13135.46,5611 h60
  text "PER" at 11603.23,5493 h60
  text "IPC-D-275 CLASS 2 LEVEL C" at 11823.23,5493 h60
  text "MIL, HOLES" at 13311.46,5380.71 h60
  text "+/-" at 12919,5380 h60
  text "+/-" at 13773,5380 h60
  text "REGISTRATION TOLERANCES:" at 11403.23,5375 h60
  text "METAL" at 12603,5375 h60
  text "5" at 13179.2,5375 h60
  text "3" at 14012.2,5375 h60
  text "MIL" at 14128.46,5375 h60
  text "+/-" at 13773,5262 h60
  text "HOLE SIZE TOLERANCE (UNLESS OTHERWISE SPECIFIED):" at 11403.23,5257 h60
  text "3" at 14012.2,5257 h60
  text "MIL" at 14128.46,5257 h60
  text "MATERIAL:" at 11328.46,5047.54 h60
  text "FR-4 High Tg" at 12314.9,4907.21 h60
  text "FR-408" at 11749.46,4898.64 h60
  text "OTHER" at 13237.46,4898.64 h60
  text "X" at 12160,4895 h60
  text "62 MIL (1.6mm) +/-10%" at 12069.56,4735.92 h60
  text "THICKNESS:" at 11403.23,4731.64 h60
  text "X" at 11941.4,4731.64 h60
  text "OTHER" at 13354.46,4731.64 h60
  text "TOLERANCE:" at 11403.23,4573.64 h60
  text "X" at 12242.53,4573.64 h60
  text "ANSI IPC-6012 TYPE 3 CLASS 2" at 12429.48,4573.64 h60
  text "OTHER +/-" at 12429.46,4417.64 h60
  text "BOW & TWIST:" at 11403.23,4260.64 h60
  text "X" at 12242.53,4260.64 h60
  text "ANSI IPC-6012 TYPE 3 CLASS 2" at 12429.48,4260.64 h60
  text "OTHER +/-" at 12429.46,4102.13 h60
  text "DRILLING:" at 11328.46,3963.64 h60
  text "REFERENCE:" at 11403.23,3846.64 h60
  text "X" at 12051.46,3846.64 h60
  text "AS SHOWN" at 12238.46,3846.64 h60
  text "X" at 12952.46,3846.64 h60
  text "NC_DRILL FILES" at 13089.46,3846.64 h60
  text "PTH COPPER THICKNESS:" at 11403.23,3688.64 h60
  text "X" at 12533.46,3688.64 h60
  text "20-30 um" at 12670.46,3688.64 h60
  text "OTHER" at 13387.46,3688.64 h60
  text "BOARD FINISH:" at 11328.46,3529.64 h60
  text "SILKSCREEN:" at 11483.68,3411.64 h60
  text "X" at 12432.46,3411.64 h60
  text "TOP" at 12558.46,3411.64 h60
  text "X" at 12942.46,3411.64 h60
  text "BOTTOM" at 13069.46,3411.64 h60
  text "SILKSCREEN COLOR:" at 11483.68,3244.64 h60
  text "X" at 12431.42,3244.64 h60
  text "WHITE" at 12558.46,3244.64 h60
  text "OTHER" at 13069.46,3244.64 h60
  text "X" at 12562.42,3085.44 h60
  text "GREEN" at 12689.46,3085.44 h60
  text "OTHER" at 13307.46,3085.44 h60
  text "SOLDER RESIST COLOR:" at 11483.68,3074.64 h60
  text "X" at 12562.42,2915.44 h60
  text "MATTE" at 12689.46,2915.44 h60
  text "SEMI-GLOSS" at 13307,2914.8 h60
  text "IMMERSION GOLD (ENIG)" at 12389.46,2726.92 h60
  text "ENEPIG" at 13727,2723.64 h60
  text "SURFACE FINISH:" at 11328.46,2722.64 h60
  text "X" at 12202.51,2722.64 h60
  text "IMM. TIN/SILVER OR EQUIV" at 11658,2565.64 h60
  text "OTHER" at 13089.46,2565.64 h60
  text "ARRAY/PANEL:" at 11328.46,2386.64 h60
  text "X" at 12200,2385 h60
  text "CUT AND TRIM PER M1 BOARD OUTLINE" at 12389.46,2382.35 h60
  text "N.C. ROUTE" at 12389.46,2230.64 h60
  text "V. SCORE" at 13255.46,2230.64 h60
  text "CERTIFICATION:" at 11328.46,2093.64 h60
  text "MATERIALS AND WORKMANSHIP FOR ALL PCBS" at 12053.46,2093.64 h60
  text "TO MEET OR EXCEED THE REQUIREMENTS OF:" at 12053.46,1995.64 h60
  text "X" at 11679.96,1859.13 h60
  text "ANSI IPC-A-600F CLASS ->" at 11818.96,1859.13 h60
  text "X" at 13458.02,1859.13 h60
  text "2" at 13576.96,1859.14 h60
  text "1" at 13261.96,1857.64 h60
  text "3" at 13930.96,1857.64 h60
  text "X" at 12494.02,1699.64 h60
  text "RoHS" at 12630.96,1699.64 h60
  text "OTHER" at 13275.36,1699.64 h60
  text "PER ORDER" at 13672.42,1699.64 h60
  text "ALL BOARDS MUST MEET OR EXCEED UL94-V0 REQUIREMENTS." at 11356,1534 h60
  text "PCB MUST BEAR THE UL94V-0 UL REGISTERED MATERIAL ID NUMBER" at 11356,1414 h60
  text "ADDITIONAL REQUIREMENTS:" at 11328.46,1240.64 h60
  text "MICROSECTION:" at 11403.23,1125.64 h60
  text "YES" at 12308.96,1125.64 h60
  text "REQUIRED" at 13170.46,969.49 h60
  text "BARE BOARD ELEC. TEST:" at 11403.23,966.64 h60
  text "NONE" at 12708.96,966.64 h60
  text "PER ORDER" at 13762.46,966.64 h60
  text "X" at 13630,965 h60
  text ".Layer_Name" at 577,-858.49 h60
M11 Gerber Information:
  lines w10: -292,-930.17 6308,-930.17 ; -292,-726.83 6310,-726.83 ; -292,-523.5 -292,-1133.5 3713,-1133.5 6310,-1133.5 6310,-523.5 -291.5,-523.5 -291.5,-1133.5 1284,-1133.5 ; 2173,-1133.5 2173,-523.5 ; 3440,-726.83 3440,-523.5 ; 4280,-726.83 4280,-523.5 ; 4902,-1140 4902,-937.17
  text "ALL ARTWORK VIEWED FROM TOP SIDE" at -228.5,-655.67 h60
  text "BOARD #:" at 2248,-655.67 h60
  text ".PRJ_Number" at 2793.5,-655.67 h60
  text "REV:" at 3638,-655.67 h60
  text ".PCB_Rev" at 3929.5,-655.67 h60
  text "SVN REV:" at 4476,-655.67 h60
  text ".VersionControl_RevNumber" at 4982,-655.67 h60
  text "LAYER NAME =" at -228.5,-858.49 h60
  text "TID #:" at 2248,-859 h60
  text ".TID" at 2793.5,-859 h60
  text "PLOT NAME =" at -228.5,-1064.34 h60
  text ".plot_File_Name" at 577,-1064.34 h60
  text "GENERATED    :" at 2250,-1064.34 h60
  text ".Print_Date" at 3119.5,-1064.34 h60
  text ".Print_Time" at 3848.5,-1064.34 h60
  text "TEXAS INSTRUMENTS" at 5113,-1064.34 h60
M12 Stackup:
  drawing of 295 lines, arcs and shapes, not listed
  text "Layer" at 9798.08,7830 h60
  text "Name" at 10207.99,7830 h60
  text "Material" at 11147.73,7830 h60
  text "Thickness" at 12007.5,7830 h60
  text "Constant" at 12657.33,7830 h60
  text "Board Layer Stack" at 13227.19,7830 h60
  text "1" at 9798.08,7710 h60
  text "Top Overlay" at 10207.99,7710 h60
  text "2" at 9798.08,7590 h60
  text "Top Solder" at 10207.99,7590 h60
  text "Solder Resist" at 11147.73,7590 h60
  text "0.40mil" at 12007.5,7590 h60
  text "3.5" at 12657.33,7590 h60
  text "3" at 9798.08,7470 h60
  text "Top Layer" at 10207.99,7470 h60
  text "Copper" at 11147.73,7470 h60
  text "2.80mil" at 12007.5,7470 h60
  text "4" at 9798.08,7350 h60
  text "Dielectric1" at 10207.99,7350 h60
  text "FR-4" at 11147.73,7350 h60
  text "12.00mil" at 12007.5,7350 h60
  text "4.2" at 12657.33,7350 h60
  text "5" at 9798.08,7230 h60
  text "GND" at 10207.99,7230 h60
  text "Copper" at 11147.73,7230 h60
  text "2.80mil" at 12007.5,7230 h60
  text "6" at 9798.08,7110 h60
  text "Dielectric 3" at 10207.99,7110 h60
  text "FR-4" at 11147.73,7110 h60
  text "26.00mil" at 12007.5,7110 h60
  text "4.2" at 12657.33,7110 h60
  text "7" at 9798.08,6990 h60
  text "Signal Layer 2" at 10207.99,6990 h60
  text "Copper" at 11147.73,6990 h60
  text "2.80mil" at 12007.5,6990 h60
  text "8" at 9798.08,6870 h60
  text "Dielectric 2" at 10207.99,6870 h60
  text "FR-4" at 11147.73,6870 h60
  text "12.00mil" at 12007.5,6870 h60
  text "4.2" at 12657.33,6870 h60
  text "9" at 9798.08,6750 h60
  text "Bottom Layer" at 10207.99,6750 h60
  text "Copper" at 11147.73,6750 h60
  text "2.80mil" at 12007.5,6750 h60
  text "10" at 9798.08,6630 h60
  text "Bottom Solder" at 10207.99,6630 h60
  text "Solder Resist" at 11147.73,6630 h60
  text "0.40mil" at 12007.5,6630 h60
  text "3.5" at 12657.33,6630 h60
  text "11" at 9798.08,6510 h60
  text "Bottom Overlay" at 10207.99,6510 h60
  text ".Layer_Name" at 577,-858.49 h60
M13 Component Bodies Top:
  text ".Layer_Name" at 577,-858.49 h60
M14 Component Bodies Bottom:
  text ".Layer_Name" at 577,-858.49 h60
M15 Courtyards Top:
  text ".Layer_Name" at 577,-858.49 h60
M16 Courtyards Bottom:
  text ".Layer_Name" at 577,-858.49 h60
Drill Drawing:
  circle w10: c8228.55,2720.27 r17.86
  circle w10: c8228.55,2720.27 r29.76
  circle w10: c8228.55,2452.44 r29.76
  circle w1: c8546.61,4790.62 r24.89
  lines w1: 8520,4660 8544.26,4611.49 8568.51,4660 8520,4660
  lines w10: 8198.79,2154.84 8228.55,2169.72 8258.31,2154.84 8243.43,2184.6 8258.31,2214.36 8228.55,2199.48 8198.79,2214.36 8213.67,2184.6 8198.79,2154.84 ; 8198.79,2288.76 8258.31,2288.76 8258.31,2348.28 8198.79,2348.28 8198.79,2288.76 ; 8198.79,2616.11 8258.31,2616.11 8228.55,2556.59 8198.79,2616.11 ; 8210.7,2166.75 8228.55,2175.68 8246.41,2166.75 8237.48,2184.6 8246.41,2202.46 8228.55,2193.53 8210.7,2202.46 8219.62,2184.6 8210.7,2166.75
  lines w12: 8145.08,2114.67 10274.83,2114.67 ; 8145.08,2784.25 10274.83,2784.25 ; 8453.89,4567.83 10518.16,4567.83 ; 8453.89,4858.89 10518.16,4858.89 ; 8508.92,1980.75 8508.92,2918.17 ; 8814.85,4422.3 8814.85,5004.42 ; 8866.39,1980.75 8866.39,2918.17 ; 9162.8,4422.3 9162.8,5004.42 ; 9551.68,1980.75 9551.68,2918.17 ; 9807.57,4422.3 9807.57,5004.42 ; 9830.7,1980.75 9830.7,2918.17 ; 10084.5,4422.3 10084.5,5004.42 ; 8145.08,1980.75 10274.83,1980.75 10274.83,2918.17 8145.08,2918.17 8145.08,1980.75 ; 8453.89,4422.3 8453.89,5004.42 10518.16,5004.42 10518.16,4422.3 8453.89,4422.3
  text "Symbol" at 8543.48,4915.06 h72
  text "Quantity" at 8869.05,4915.06 h72
  text "Finished Hole Size" at 9226.05,4915.06 h72
  text "Plated" at 9887.61,4915.06 h72
  text "Hole Type" at 10171.75,4915.06 h72
  text "10" at 8869.05,4765.74 h60
  text "7.87mil (0.200mm)" at 9226.05,4765.74 h60
  text "PTH" at 9887.61,4765.74 h60
  text "Round" at 10171.75,4765.74 h60
  text "2" at 8869.05,4616.42 h60
  text "214.57mil (5.450mm)" at 9226.05,4616.42 h60
  text "PTH" at 9887.61,4616.42 h60
  text "Round" at 10171.75,4616.42 h60
  text "12 Total" at 8869.05,4467.1 h60
  text "Symbol" at 8225.43,2824.42 h77.57
  text "Quantity" at 8549.1,2824.42 h77.57
  text "Finished Hole Size" at 8906.56,2824.42 h77.57
  text "Plated" at 9591.85,2824.42 h77.57
  text "Hole Type" at 9870.87,2824.42 h77.57
  text "196" at 8549.1,2690.51 h64.64
  text "10.00mil (0.254mm)" at 8906.56,2690.51 h64.64
  text "PTH" at 9591.85,2690.51 h64.64
  text "Round" at 9870.87,2690.51 h64.64
  text "466" at 8549.1,2556.59 h64.64
  text "20.00mil (0.508mm)" at 8906.56,2556.59 h64.64
  text "PTH" at 9591.85,2556.59 h64.64
  text "Round" at 9870.87,2556.59 h64.64
  text "12" at 8549.1,2422.68 h64.64
  text "30.00mil (0.762mm)" at 8906.56,2422.68 h64.64
  text "PTH" at 9591.85,2422.68 h64.64
  text "Round" at 9870.87,2422.68 h64.64
  text "6" at 8549.1,2288.76 h64.64
  text "63.00mil (1.600mm)" at 8906.56,2288.76 h64.64
  text "PTH" at 9591.85,2288.76 h64.64
  text "Round" at 9870.87,2288.76 h64.64
  text "4" at 8549.1,2154.84 h64.64
  text "125.98mil (3.200mm)" at 8906.56,2154.84 h64.64
  text "PTH" at 9591.85,2154.84 h64.64
  text "Round" at 9870.87,2154.84 h64.64
  text "684 Total" at 8549.1,2020.93 h64.64
  text ".Layer_Name" at 577,-858.49 h60

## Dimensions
0,0 to 4400,0 on M2 Board Dimensions
0,0 to 0,7000 on M2 Board Dimensions
0,-400 to 1000,-400 on M2 Board Dimensions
